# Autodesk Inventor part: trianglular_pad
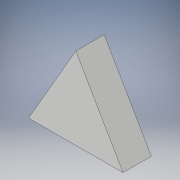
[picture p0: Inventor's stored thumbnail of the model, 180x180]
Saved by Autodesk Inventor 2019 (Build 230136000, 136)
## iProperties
Created: 2020-02
Part Number: trianglular_pad
Material: Generic
Document SubType Name: Modeling
Designer: Siddharth
Density: 1 g/cm^3
Appearance: Default
Author: Siddharth
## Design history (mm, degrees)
sketch "Sketch1"
  geometry: L1 (0, 0)-(50, 0); L2 (0, 0)-(0, 86.6); L3 (0, 86.6)-(50, 0); L4 (0, 86.6)-(-50, 0); L5 (0, 0)-(-50, 0)
  constraints: 10 end point, 1 horizontal, 1 symmetric about line, 1 vertical
  dimensions: "d0" = 50 distance of L1.start L1.end; "d1" = 86.6 distance of L1.start L2.end
extrude "Extrusion1" new body sketch "Sketch1" distance "d2" = 30; taper "d3" = 0 deg
body "Solid1"
